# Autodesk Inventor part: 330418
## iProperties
Shininess: 80.0
Length Units: 11269
Angle Units: 11279
Time Units: 11290
Mass Units: 11284
Length Display Precision: 3
Angle Display Precision: 2
Compacted: True
Company: Pneumax S.p.A.
Part Number: 330418
Material: Default
Description: ASTA DOPPIA+ANELLO GIREVOLE Ø4 G1/8"
Document SubType Name: Modellazione
Catalog Web Link: www.pneumaxspa.com
Density: 1.59
Volumn: 0.8648857994912436
Area: 17.092995283760587
PropertySet Name: Model Information
Control State: 0
Master: False
Checked Out: False
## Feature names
1. Smusso11 [Chamfer]
2. Revolution6
3. Rivoluzione7 [Revolution]
4. Estrusione12 [Extrusion]
5. Smusso10 [Chamfer]
6. Foro7 [Hole]
7. Estrusione11 [Extrusion]
8. Foro6 [Hole]
9. Serie rettangolare1 [Rectangular Pattern]
10. Serie rettangolare2 [Rectangular Pattern]
11. Foro8 [Hole]
